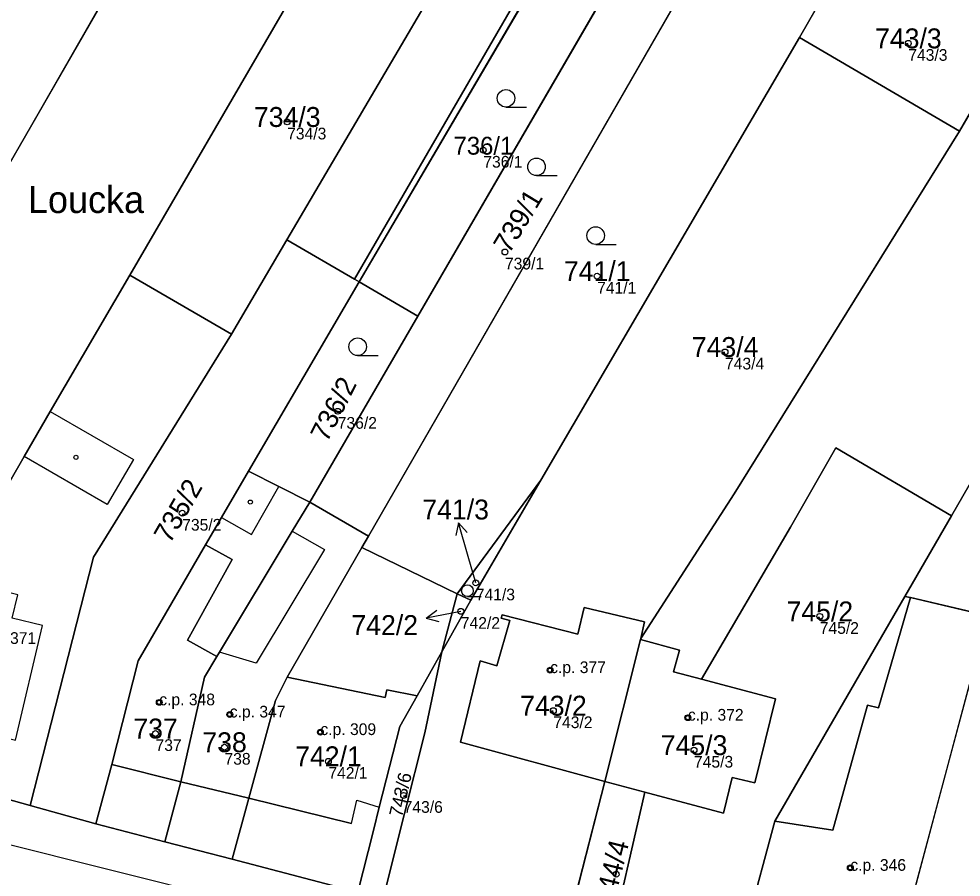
# Model space of a CAD drawing. Extents: x -603967 to -594699, y -1179315 to -1165625.
# Drawn here: x -598248.8 to -598168.4, y -1172235.7 to -1172162.4 of the extents above; entities that cross this region are included whole.
import ezdxf

# ---------------------------------------------------------------- set-up
doc = ezdxf.new("R2010")
doc.units = 0
for name, color, linetype in [('Definiční body', 7, 'Continuous'), ('Hranice parcel', 7, 'Continuous'), ('Parcelní čísla', 7, 'Continuous'), ('Polygon budovy', 7, 'Continuous'), ('Polygon parcely', 7, 'Continuous'), ('Pop  PČ popisy', 7, 'Continuous'), ('Vnitřní kresba', 7, 'Continuous'), ('Značky budov', 7, 'Continuous'), ('Značky kultur', 7, 'Continuous')]:
    doc.layers.add(name, color=color, linetype=linetype)

msp = doc.modelspace()

# ---------------------------------------------------------------- linework, layer by layer
at = {"layer": 'Definiční body'}
for centre in [(-598172.88, -1172164.46994), (-598225.92, -1172171.17994), (-598209.17, -1172173.58994), (-598207.32, -1172182.27994), (-598199.45, -1172184.33994), (-598188.53, -1172190.81994), (-598221.6, -1172195.87994), (-598234.88, -1172204.57994), (-598209.81, -1172210.52994), (-598211.09, -1172212.95994), (-598180.44, -1172213.38994), (-598203.46, -1172217.97994), (-598236.84, -1172220.72994), (-598230.82, -1172221.76994), (-598203.19, -1172221.43994), (-598191.7, -1172222.03994), (-598237.16, -1172223.38994), (-598223.08, -1172223.26994), (-598231.27, -1172224.55994), (-598191.18, -1172224.80994), (-598222.4, -1172225.75994), (-598215.97, -1172228.66994), (-598197.82, -1172235.39994), (-598177.83, -1172234.85994)]:
    msp.add_circle(centre, 0.25, dxfattribs=at)
at = {"layer": 'Hranice parcel'}
for p, q in [((-598262.73, -1172197.4), (-598180.62, -1172054.99)), ((-598148.39, -1172063.07), (-598219.76, -1172184.84)), ((-598220.16, -1172184.61), (-598170.52, -1172098.93)), ((-598239.34, -1172184.27), (-598213.34, -1172139.51)), ((-598225.94, -1172181.25), (-598204.45, -1172144.67)), ((-598214.76, -1172187.75), (-598193.87, -1172151.8)), ((-598218.98, -1172206.53), (-598189.04, -1172154.51)), ((-598178.88, -1172158.2), (-598182.17, -1172163.97)), ((-598162.53, -1172161.65), (-598168.51, -1172171.97)), ((-598182.17, -1172163.97), (-598204.25, -1172201.77)), ((-598182.17, -1172163.97), (-598168.51, -1172171.97)), ((-598169.2, -1172204.81), (-598147.43, -1172167.06)), ((-598230.67, -1172189.31), (-598225.94, -1172181.25)), ((-598225.94, -1172181.25), (-598220.16, -1172184.61)), ((-598230.67, -1172189.31), (-598239.34, -1172184.27)), ((-598219.76, -1172184.84), (-598220.16, -1172184.61)), ((-598229.22, -1172200.98), (-598219.76, -1172184.84)), ((-598219.76, -1172184.84), (-598214.76, -1172187.75)), ((-598223.99, -1172203.63), (-598214.76, -1172187.75)), ((-598211.39, -1172211.46), (-598204.25, -1172201.77)), ((-598204.25, -1172201.77), (-598210.24, -1172212.01)), ((-598218.98, -1172206.53), (-598223.99, -1172203.63)), ((-598173.17, -1172211.68), (-598169.2, -1172204.81)), ((-598190.53, -1172218.76), (-598182.93, -1172205.76)), ((-598219.55, -1172207.52), (-598218.98, -1172206.53)), ((-598219.55, -1172207.52), (-598211.39, -1172211.46)), ((-598212.71, -1172216.41), (-598211.39, -1172211.46)), ((-598211.39, -1172211.46), (-598210.24, -1172212.01)), ((-598172.7, -1172211.79), (-598173.17, -1172211.68)), ((-598166.08, -1172213.33), (-598172.7, -1172211.79)), ((-598210.24, -1172212.01), (-598212.71, -1172216.41)), ((-598195.4, -1172213.85), (-598195.72, -1172215.27)), ((-598195.74, -1172215.37), (-598198.8, -1172227.49)), ((-598195.72, -1172215.27), (-598195.74, -1172215.37)), ((-598214.82, -1172220.18), (-598212.71, -1172216.41)), ((-598212.71, -1172216.41), (-598214.17, -1172223.33)), ((-598214.17, -1172223.33), (-598215.91, -1172230.22)), ((-598198.8, -1172227.49), (-598211.12, -1172224.13)), ((-598236.36, -1172232.63), (-598235, -1172227.52)), ((-598198.8, -1172227.49), (-598202.31, -1172241.23)), ((-598195.39, -1172228.4), (-598198.8, -1172227.49)), ((-598198.53, -1172242.16), (-598195.39, -1172228.4)), ((-598242.25, -1172231.09), (-598247.86, -1172229.53)), ((-598230.62, -1172234.12), (-598229.18, -1172228.9)), ((-598215.91, -1172230.22), (-598217.72, -1172237.46)), ((-598236.36, -1172232.63), (-598242.25, -1172231.09)), ((-598230.62, -1172234.12), (-598236.36, -1172232.63)), ((-598219.87, -1172236.93), (-598230.62, -1172234.12))]:
    msp.add_line(p, q, dxfattribs=at)
for points in [[(-598168.51, -1172171.97), (-598187.75, -1172202.92), (-598195.72, -1172215.27)], [(-598254.41, -1172210.21), (-598248.38, -1172199.75), (-598246.15, -1172195.9), (-598239.34, -1172184.27)], [(-598247.86, -1172229.53), (-598242.46, -1172208.34), (-598230.67, -1172189.31)], [(-598182.93, -1172205.76), (-598179.08, -1172199.01), (-598169.2, -1172204.81)], [(-598242.25, -1172231.09), (-598240.89, -1172226.04), (-598238.63, -1172217.19), (-598232.88, -1172207.29), (-598231.52, -1172204.95), (-598229.22, -1172200.98)], [(-598229.22, -1172200.98), (-598226.63, -1172202.29), (-598223.99, -1172203.63)], [(-598235, -1172227.52), (-598232.98, -1172218.58), (-598231.92, -1172216.82), (-598231.7, -1172216.45), (-598225.49, -1172206.12), (-598223.99, -1172203.63)], [(-598229.18, -1172228.9), (-598226.91, -1172220.56), (-598225.92, -1172218.59), (-598219.55, -1172207.52)], [(-598187.86, -1172244.77), (-598186.64, -1172239.63), (-598184.27, -1172230.87), (-598173.17, -1172211.68)], [(-598211.12, -1172224.13), (-598209.45, -1172217.18), (-598208.02, -1172217.6), (-598206.91, -1172213.75), (-598207.63, -1172213.55), (-598207.55, -1172213.26), (-598201.09, -1172214.92), (-598200.55, -1172212.64), (-598195.4, -1172213.85)], [(-598195.74, -1172215.37), (-598192.42, -1172216.27), (-598192.92, -1172218.13), (-598190.53, -1172218.76)], [(-598190.53, -1172218.76), (-598184.23, -1172220.42), (-598185.98, -1172227.61), (-598187.92, -1172227.14), (-598188.67, -1172230.2), (-598195.39, -1172228.4)], [(-598219.87, -1172236.93), (-598218.56, -1172231.67), (-598218.05, -1172229.68), (-598216.3, -1172222.79), (-598214.82, -1172220.18)], [(-598258.93, -1172226.53), (-598251.97, -1172228.39), (-598247.86, -1172229.53)]]:
    msp.add_lwpolyline(points, dxfattribs=at)
at = {"layer": 'Polygon budovy'}
for points in [[(-598176.41, -1172153.86), (-598178.88, -1172158.2), (-598182.17, -1172163.97), (-598168.51, -1172171.97), (-598162.53, -1172161.65), (-598176.37, -1172153.79)], [(-598232.98, -1172218.58), (-598235, -1172227.52), (-598229.18, -1172228.9), (-598226.91, -1172220.56), (-598225.92, -1172218.59), (-598219.55, -1172207.52), (-598218.98, -1172206.53), (-598223.99, -1172203.63), (-598225.49, -1172206.12), (-598222.74, -1172207.69), (-598228.56, -1172217.37), (-598231.7, -1172216.45), (-598231.92, -1172216.82)], [(-598238.63, -1172217.19), (-598240.89, -1172226.04), (-598235, -1172227.52), (-598232.98, -1172218.58), (-598231.92, -1172216.82), (-598234.44, -1172215.43), (-598230.62, -1172208.54), (-598232.88, -1172207.29)], [(-598246.82, -1172214.18), (-598249.41, -1172213.55), (-598248.93, -1172211.54), (-598254.41, -1172210.21), (-598255.39, -1172212.06), (-598257.77, -1172221.76), (-598249.13, -1172223.96)], [(-598186.64, -1172239.63), (-598173.98, -1172242.88), (-598166.08, -1172213.33), (-598172.7, -1172211.79), (-598175.43, -1172221.2), (-598176.37, -1172220.97), (-598179.33, -1172231.65), (-598184.27, -1172230.87)], [(-598209.45, -1172217.18), (-598211.12, -1172224.13), (-598198.8, -1172227.49), (-598195.74, -1172215.37), (-598195.72, -1172215.27), (-598195.4, -1172213.85), (-598200.55, -1172212.64), (-598201.09, -1172214.92), (-598207.55, -1172213.26), (-598207.63, -1172213.55), (-598206.91, -1172213.75), (-598208.02, -1172217.6)], [(-598198.8, -1172227.49), (-598195.39, -1172228.4), (-598188.67, -1172230.2), (-598187.92, -1172227.14), (-598185.98, -1172227.61), (-598184.23, -1172220.42), (-598190.53, -1172218.76), (-598192.92, -1172218.13), (-598192.42, -1172216.27), (-598195.74, -1172215.37)], [(-598229.18, -1172228.9), (-598220.42, -1172231.08), (-598219.98, -1172229.08), (-598218.05, -1172229.68), (-598216.3, -1172222.79), (-598214.82, -1172220.18), (-598217.42, -1172219.65), (-598217.56, -1172220.3), (-598225.92, -1172218.59), (-598226.91, -1172220.56)]]:
    msp.add_lwpolyline(points, close=True, dxfattribs=at)
at = {"layer": 'Polygon parcely'}
for points in [[(-598180.62, -1172054.99), (-598192.13, -1172052.55), (-598253.54, -1172158.49), (-598272.77, -1172191.84), (-598269.91, -1172193.42), (-598262.73, -1172197.4)], [(-598166.85, -1172058.43), (-598180.62, -1172054.99), (-598262.73, -1172197.4), (-598268.58, -1172207.73), (-598271.3, -1172218.4), (-598272.52, -1172223.46), (-598258.93, -1172226.53), (-598257.77, -1172221.76), (-598261.07, -1172220.89), (-598266.88, -1172219.49), (-598266.29, -1172217.47), (-598267.91, -1172217), (-598266, -1172209.02), (-598264.65, -1172207.75), (-598263.54, -1172208.02), (-598263.25, -1172206.79), (-598260.22, -1172207.52), (-598260.52, -1172208.74), (-598254.41, -1172210.21), (-598248.38, -1172199.75), (-598246.15, -1172195.9), (-598239.34, -1172184.27), (-598213.34, -1172139.51)], [(-598220.16, -1172184.61), (-598170.52, -1172098.93), (-598149.51, -1172062.78), (-598155.91, -1172061.14), (-598204.45, -1172144.67), (-598225.94, -1172181.25)], [(-598148.39, -1172063.07), (-598149.51, -1172062.78), (-598170.52, -1172098.93), (-598220.16, -1172184.61), (-598219.76, -1172184.84)], [(-598148.39, -1172063.07), (-598219.76, -1172184.84), (-598214.76, -1172187.75), (-598193.87, -1172151.8), (-598143.12, -1172064.42)], [(-598230.67, -1172189.31), (-598225.94, -1172181.25), (-598204.45, -1172144.67), (-598213.34, -1172139.51), (-598239.34, -1172184.27)], [(-598145.09, -1172205.5), (-598118.02, -1172158.65), (-598136.44, -1172148.04), (-598147.43, -1172167.06), (-598169.2, -1172204.81), (-598173.17, -1172211.68), (-598172.7, -1172211.79), (-598166.08, -1172213.33), (-598162.21, -1172215.46), (-598157.29, -1172206.36), (-598154.17, -1172200.59)], [(-598189.04, -1172154.51), (-598193.87, -1172151.8), (-598214.76, -1172187.75), (-598223.99, -1172203.63), (-598218.98, -1172206.53)], [(-598219.55, -1172207.52), (-598211.39, -1172211.46), (-598204.25, -1172201.77), (-598182.17, -1172163.97), (-598178.88, -1172158.2), (-598188.11, -1172152.89), (-598189.04, -1172154.51), (-598218.98, -1172206.53)], [(-598178.88, -1172158.2), (-598182.17, -1172163.97), (-598168.51, -1172171.97), (-598162.53, -1172161.65), (-598176.37, -1172153.79), (-598176.41, -1172153.86)], [(-598147.43, -1172167.06), (-598161.09, -1172159.16), (-598162.53, -1172161.65), (-598168.51, -1172171.97), (-598187.75, -1172202.92), (-598195.72, -1172215.27), (-598195.74, -1172215.37), (-598192.42, -1172216.27), (-598192.92, -1172218.13), (-598190.53, -1172218.76), (-598182.93, -1172205.76), (-598179.08, -1172199.01), (-598169.2, -1172204.81)], [(-598217.72, -1172237.46), (-598202.31, -1172241.23), (-598198.8, -1172227.49), (-598211.12, -1172224.13), (-598209.45, -1172217.18), (-598208.02, -1172217.6), (-598206.91, -1172213.75), (-598207.63, -1172213.55), (-598207.55, -1172213.26), (-598201.09, -1172214.92), (-598200.55, -1172212.64), (-598195.4, -1172213.85), (-598195.72, -1172215.27), (-598187.75, -1172202.92), (-598168.51, -1172171.97), (-598182.17, -1172163.97), (-598204.25, -1172201.77), (-598210.24, -1172212.01), (-598212.71, -1172216.41), (-598214.17, -1172223.33), (-598215.91, -1172230.22)], [(-598219.76, -1172184.84), (-598220.16, -1172184.61), (-598225.94, -1172181.25), (-598230.67, -1172189.31), (-598242.46, -1172208.34), (-598247.86, -1172229.53), (-598242.25, -1172231.09), (-598240.89, -1172226.04), (-598238.63, -1172217.19), (-598232.88, -1172207.29), (-598231.52, -1172204.95), (-598229.22, -1172200.98)], [(-598247.86, -1172229.53), (-598242.46, -1172208.34), (-598230.67, -1172189.31), (-598239.34, -1172184.27), (-598246.15, -1172195.9), (-598248.38, -1172199.75), (-598254.41, -1172210.21), (-598255.39, -1172212.06), (-598257.77, -1172221.76), (-598258.93, -1172226.53), (-598251.97, -1172228.39)], [(-598223.99, -1172203.63), (-598214.76, -1172187.75), (-598219.76, -1172184.84), (-598229.22, -1172200.98), (-598226.63, -1172202.29)], [(-598169.2, -1172204.81), (-598179.08, -1172199.01), (-598182.93, -1172205.76), (-598190.53, -1172218.76), (-598184.23, -1172220.42), (-598185.98, -1172227.61), (-598187.92, -1172227.14), (-598188.67, -1172230.2), (-598195.39, -1172228.4), (-598198.53, -1172242.16), (-598187.86, -1172244.77), (-598186.64, -1172239.63), (-598184.27, -1172230.87), (-598173.17, -1172211.68)], [(-598173.17, -1172211.68), (-598184.27, -1172230.87), (-598186.64, -1172239.63), (-598187.86, -1172244.77), (-598166.74, -1172250.14), (-598165.28, -1172245.04), (-598163.13, -1172236.55), (-598155.73, -1172224), (-598153.51, -1172220.14), (-598152.29, -1172218.03), (-598145.09, -1172205.5), (-598154.17, -1172200.59), (-598157.29, -1172206.36), (-598162.21, -1172215.46), (-598166.08, -1172213.33), (-598172.7, -1172211.79)], [(-598242.25, -1172231.09), (-598236.36, -1172232.63), (-598235, -1172227.52), (-598232.98, -1172218.58), (-598231.92, -1172216.82), (-598231.7, -1172216.45), (-598225.49, -1172206.12), (-598223.99, -1172203.63), (-598226.63, -1172202.29), (-598229.22, -1172200.98), (-598231.52, -1172204.95), (-598232.88, -1172207.29), (-598238.63, -1172217.19), (-598240.89, -1172226.04)], [(-598211.39, -1172211.46), (-598210.24, -1172212.01), (-598204.25, -1172201.77)], [(-598219.55, -1172207.52), (-598218.98, -1172206.53), (-598223.99, -1172203.63), (-598225.49, -1172206.12), (-598231.7, -1172216.45), (-598231.92, -1172216.82), (-598232.98, -1172218.58), (-598235, -1172227.52), (-598236.36, -1172232.63), (-598230.62, -1172234.12), (-598229.18, -1172228.9), (-598226.91, -1172220.56), (-598225.92, -1172218.59)], [(-598230.62, -1172234.12), (-598219.87, -1172236.93), (-598218.56, -1172231.67), (-598218.05, -1172229.68), (-598216.3, -1172222.79), (-598214.82, -1172220.18), (-598212.71, -1172216.41), (-598211.39, -1172211.46), (-598219.55, -1172207.52), (-598225.92, -1172218.59), (-598226.91, -1172220.56), (-598229.18, -1172228.9)], [(-598212.71, -1172216.41), (-598210.24, -1172212.01), (-598211.39, -1172211.46)], [(-598195.74, -1172215.37), (-598195.72, -1172215.27), (-598195.4, -1172213.85), (-598200.55, -1172212.64), (-598201.09, -1172214.92), (-598207.55, -1172213.26), (-598207.63, -1172213.55), (-598206.91, -1172213.75), (-598208.02, -1172217.6), (-598209.45, -1172217.18), (-598211.12, -1172224.13), (-598198.8, -1172227.49)], [(-598195.74, -1172215.37), (-598198.8, -1172227.49), (-598195.39, -1172228.4), (-598188.67, -1172230.2), (-598187.92, -1172227.14), (-598185.98, -1172227.61), (-598184.23, -1172220.42), (-598190.53, -1172218.76), (-598192.92, -1172218.13), (-598192.42, -1172216.27)], [(-598214.17, -1172223.33), (-598212.71, -1172216.41), (-598214.82, -1172220.18), (-598216.3, -1172222.79), (-598218.05, -1172229.68), (-598218.56, -1172231.67), (-598219.87, -1172236.93), (-598217.72, -1172237.46), (-598215.91, -1172230.22)], [(-598195.39, -1172228.4), (-598198.8, -1172227.49), (-598202.31, -1172241.23), (-598198.53, -1172242.16)]]:
    msp.add_lwpolyline(points, close=True, dxfattribs=at)
msp.add_lwpolyline([(-598073.47, -1172274.19), (-598073.16, -1172271.95), (-598078.41, -1172271.53), (-598082.86, -1172271.28), (-598090.48, -1172269.19), (-598101.84, -1172266.14), (-598112.46, -1172263.54), (-598124.03, -1172260.73), (-598134.74, -1172258.12), (-598145.44, -1172255.45), (-598155.65, -1172252.91), (-598166.74, -1172250.14), (-598187.86, -1172244.77), (-598198.53, -1172242.16), (-598202.31, -1172241.23), (-598217.72, -1172237.46), (-598219.87, -1172236.93), (-598230.62, -1172234.12), (-598236.36, -1172232.63), (-598242.25, -1172231.09), (-598247.86, -1172229.53), (-598251.97, -1172228.39)], dxfattribs=at)
at = {"layer": 'Pop  PČ popisy'}
for p, q in [((-598211.297, -1172205.395), (-598211.502, -1172206.496)), ((-598210.47, -1172208.28), (-598211.297, -1172205.395)), ((-598211.297, -1172205.395), (-598210.54, -1172206.22)), ((-598209.81, -1172210.53), (-598210.47, -1172208.28)), ((-598214.036, -1172213.533), (-598213.148, -1172212.85)), ((-598211.09, -1172212.96), (-598214.036, -1172213.533)), ((-598214.036, -1172213.533), (-598212.957, -1172213.833))]:
    msp.add_line(p, q, dxfattribs=at)
at = {"layer": 'Vnitřní kresba'}
for p, q in [((-598246.15, -1172195.9), (-598239.05, -1172199.99)), ((-598241.28, -1172203.85), (-598248.38, -1172199.75)), ((-598239.05, -1172199.99), (-598241.28, -1172203.85)), ((-598228.97, -1172206.4), (-598226.63, -1172202.29)), ((-598231.52, -1172204.95), (-598228.97, -1172206.4)), ((-598225.49, -1172206.12), (-598222.74, -1172207.69)), ((-598232.88, -1172207.29), (-598230.62, -1172208.54)), ((-598222.74, -1172207.69), (-598228.56, -1172217.37)), ((-598230.62, -1172208.54), (-598234.44, -1172215.43)), ((-598175.43, -1172221.2), (-598172.7, -1172211.79)), ((-598246.82, -1172214.18), (-598249.41, -1172213.55)), ((-598173.98, -1172242.88), (-598166.08, -1172213.33)), ((-598249.13, -1172223.96), (-598246.82, -1172214.18)), ((-598234.44, -1172215.43), (-598231.92, -1172216.82)), ((-598228.56, -1172217.37), (-598231.7, -1172216.45)), ((-598225.92, -1172218.59), (-598217.56, -1172220.3)), ((-598217.56, -1172220.3), (-598217.42, -1172219.65)), ((-598217.42, -1172219.65), (-598214.82, -1172220.18)), ((-598179.33, -1172231.65), (-598176.37, -1172220.97)), ((-598176.37, -1172220.97), (-598175.43, -1172221.2)), ((-598235, -1172227.52), (-598240.89, -1172226.04)), ((-598229.18, -1172228.9), (-598235, -1172227.52)), ((-598220.42, -1172231.08), (-598229.18, -1172228.9)), ((-598220.42, -1172231.08), (-598219.98, -1172229.08)), ((-598219.98, -1172229.08), (-598218.05, -1172229.68)), ((-598231.22, -1172237.49), (-598260.03, -1172230.28)), ((-598184.27, -1172230.87), (-598179.33, -1172231.65))]:
    msp.add_line(p, q, dxfattribs=at)
at = {"layer": 'Značky budov'}
for centre in [(-598243.9568, -1172199.80916), (-598229.0668, -1172203.62916), (-598203.4668, -1172217.97916), (-598236.8468, -1172220.72916), (-598230.8268, -1172221.76916), (-598191.7068, -1172222.03916), (-598223.0868, -1172223.26916), (-598177.8368, -1172234.85916)]:
    msp.add_circle(centre, 0.175, dxfattribs=at)
at = {"layer": 'Značky kultur'}
for p, q in [((-598207.233, -1172169.91), (-598205.483, -1172169.91)), ((-598204.623, -1172175.76), (-598202.873, -1172175.76)), ((-598199.573, -1172181.63), (-598197.823, -1172181.63)), ((-598219.903, -1172191.12), (-598218.153, -1172191.12)), ((-598210.525, -1172211.7), (-598209.353, -1172211.7))]:
    msp.add_line(p, q, dxfattribs=at)
for centre, radius in [((-598207.23286, -1172169.15981), 0.75), ((-598204.62286, -1172175.00981), 0.75), ((-598199.57286, -1172180.87981), 0.75), ((-598219.90286, -1172190.36981), 0.75), ((-598210.52521, -1172211.19737), 0.5025)]:
    msp.add_circle(centre, radius, dxfattribs=at)

# ---------------------------------------------------------------- texts
at = {"layer": 'Definiční body'}
for s, p in [('743/3', (-598172.88, -1172165.959)), ('734/3', (-598225.92, -1172172.669)), ('736/1', (-598209.17, -1172175.079)), ('739/1', (-598207.32, -1172183.769)), ('741/1', (-598199.45, -1172185.829)), ('743/4', (-598188.53, -1172192.309)), ('736/2', (-598221.6, -1172197.369)), ('735/2', (-598234.88, -1172206.069)), ('741/3', (-598209.81, -1172212.019)), ('742/2', (-598211.09, -1172214.449)), ('745/2', (-598180.44, -1172214.879)), ('c.p. 371', (-598252.11, -1172215.74)), ('c.p. 377', (-598203.46, -1172218.23)), ('c.p. 348', (-598236.84, -1172220.98)), ('c.p. 347', (-598230.82, -1172222.02)), ('c.p. 372', (-598191.7, -1172222.29)), ('743/2', (-598203.19, -1172222.929)), ('c.p. 309', (-598223.08, -1172223.52)), ('737', (-598237.16, -1172224.879)), ('738', (-598231.27, -1172226.049)), ('745/3', (-598191.18, -1172226.299)), ('742/1', (-598222.4, -1172227.249)), ('743/6', (-598215.97, -1172230.159)), ('c.p. 346', (-598177.83, -1172235.11))]:
    msp.add_text(s, height=0.999996, dxfattribs=at).set_placement(p)
at = {"layer": 'Parcelní čísla'}
for s, height, p in [('743/3', 1.699998, (-598175.716, -1172164.895)), ('734/3', 1.699998, (-598228.756, -1172171.605)), ('736/1', 1.522998, (-598211.71, -1172173.97)), ('741/1', 1.699998, (-598202.286, -1172184.765)), ('743/4', 1.699998, (-598191.366, -1172191.245)), ('741/3', 1.699998, (-598214.376, -1172205.115)), ('745/2', 1.699998, (-598183.276, -1172213.815)), ('742/2', 1.699998, (-598220.432, -1172214.982)), ('743/2', 1.699998, (-598206.026, -1172221.865)), ('737', 1.699998, (-598239.05, -1172223.815)), ('738', 1.699998, (-598233.16, -1172224.985)), ('745/3', 1.699998, (-598194.016, -1172225.235)), ('742/1', 1.699998, (-598225.236, -1172226.185))]:
    msp.add_text(s, height=height, dxfattribs=at).set_placement(p)
for s, height, rotation, p in [('739/1', 1.699998, 59, (-598206.955, -1172182.498)), ('736/2', 1.699998, 63, (-598222.508, -1172198.599)), ('735/2', 1.699998, 59.9999972, (-598235.929, -1172207.248)), ('743/6', 1.138998, 77, (-598216.119, -1172230.585)), ('744/4', 1.699998, 76, (-598198.093, -1172238.254))]:
    msp.add_text(s, height=height, rotation=rotation, dxfattribs=at).set_placement(p)
at = {"layer": 'Pop  PČ popisy'}
msp.add_text('Loucka', height=2.299998, dxfattribs=at).set_placement((-598248.054, -1172178.955))

doc.saveas('drawing.dxf')
